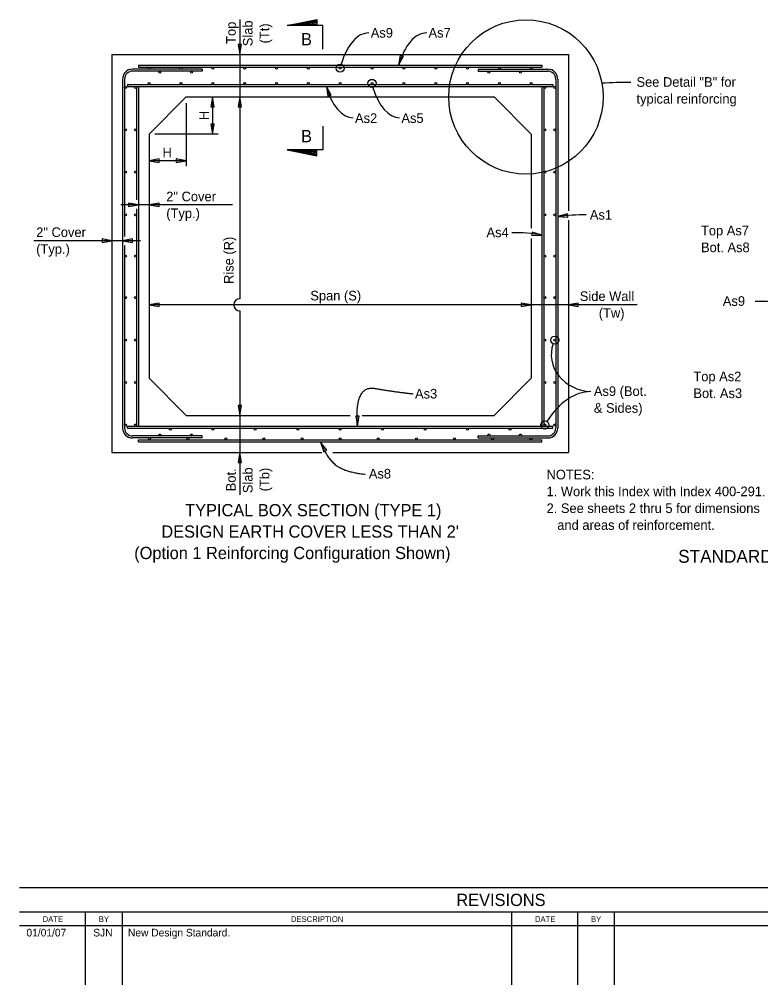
# Model space of a CAD drawing. Extents: x 10340.6 to 10393.7, y 76398.7 to 76426.2.
# Drawn here: x 10340.56 to 10352.2, y 76398.74 to 76413.9 of the extents above; entities that cross this region are included whole.
import ezdxf

# ---------------------------------------------------------------- set-up
doc = ezdxf.new("R2010")
doc.units = 0
for name, color, linetype in [('AdhocPoint_dp', 7, 'Continuous'), ('Border', 7, 'Continuous'), ('Patterning', 7, 'Continuous'), ('PlotBorder_dp', 7, 'Continuous'), ('TextMisc', 7, 'Continuous')]:
    doc.layers.add(name, color=color, linetype=linetype)

msp = doc.modelspace()

# ---------------------------------------------------------------- linework, layer by layer
at = {"layer": 'AdhocPoint_dp'}
for p, q in [((10342.427, 76413.179), (10348.76, 76413.179)), ((10342.427, 76413.179), (10342.427, 76413.148)), ((10342.427, 76413.148), (10348.76, 76413.148)), ((10348.76, 76413.179), (10348.76, 76413.148)), ((10343.427, 76413.116), (10342.333, 76413.116)), ((10343.427, 76413.085), (10342.333, 76413.085)), ((10343.427, 76413.116), (10343.427, 76413.085)), ((10347.76, 76413.116), (10348.854, 76413.116)), ((10347.76, 76413.116), (10347.76, 76413.085)), ((10347.76, 76413.085), (10348.854, 76413.085)), ((10342.177, 76412.96), (10342.177, 76407.481)), ((10342.208, 76412.96), (10342.208, 76410.487)), ((10342.252, 76412.877), (10348.935, 76412.877)), ((10342.252, 76412.877), (10342.252, 76412.845)), ((10342.252, 76412.845), (10348.935, 76412.845)), ((10342.396, 76412.845), (10342.396, 76411.063)), ((10342.427, 76412.845), (10342.427, 76407.512)), ((10348.76, 76412.845), (10348.76, 76407.512)), ((10348.76, 76412.845), (10348.76, 76407.799)), ((10348.791, 76412.845), (10348.791, 76407.512)), ((10348.935, 76412.877), (10348.935, 76412.845)), ((10348.979, 76412.96), (10348.979, 76407.481)), ((10349.01, 76412.96), (10349.01, 76407.481)), ((10342.396, 76410.921), (10342.396, 76407.512)), ((10342.208, 76410.346), (10342.208, 76407.481)), ((10342.252, 76407.512), (10348.935, 76407.512)), ((10342.252, 76407.481), (10342.252, 76407.512)), ((10348.935, 76407.481), (10348.935, 76407.512)), ((10342.252, 76407.481), (10348.935, 76407.481)), ((10343.427, 76407.356), (10342.333, 76407.356)), ((10343.427, 76407.325), (10342.333, 76407.325)), ((10342.427, 76407.293), (10348.76, 76407.293)), ((10342.427, 76407.262), (10342.427, 76407.293)), ((10342.427, 76407.262), (10348.76, 76407.262)), ((10343.427, 76407.325), (10343.427, 76407.356)), ((10347.76, 76407.325), (10347.76, 76407.356)), ((10347.76, 76407.356), (10348.854, 76407.356)), ((10347.76, 76407.325), (10348.854, 76407.325)), ((10348.76, 76407.262), (10348.76, 76407.293))]:
    msp.add_line(p, q, dxfattribs=at)
for centre in [(10342.594, 76413.132), (10343.094, 76413.132), (10343.594, 76413.132), (10344.094, 76413.132), (10344.594, 76413.132), (10345.094, 76413.132), (10345.594, 76413.132), (10346.094, 76413.132), (10346.594, 76413.132), (10347.094, 76413.132), (10347.594, 76413.132), (10348.094, 76413.132), (10348.594, 76413.132), (10342.76, 76413.07), (10343.26, 76413.07), (10347.927, 76413.07), (10348.427, 76413.07), (10342.224, 76412.83), (10342.38, 76412.83), (10342.594, 76412.892), (10343.094, 76412.892), (10343.594, 76412.892), (10344.094, 76412.892), (10344.594, 76412.892), (10345.094, 76412.892), (10345.594, 76412.892), (10346.094, 76412.892), (10346.594, 76412.892), (10347.094, 76412.892), (10347.594, 76412.892), (10348.094, 76412.892), (10348.594, 76412.892), (10348.807, 76412.83), (10348.963, 76412.83), (10342.224, 76412.163), (10342.38, 76412.163), (10348.807, 76412.163), (10348.963, 76412.163), (10342.224, 76411.497), (10342.38, 76411.497), (10348.807, 76411.497), (10348.963, 76411.497), (10342.224, 76410.83), (10342.38, 76410.83), (10348.807, 76410.83), (10348.963, 76410.83), (10342.224, 76410.179), (10342.38, 76410.179), (10348.807, 76410.179), (10348.963, 76410.179), (10342.224, 76409.528), (10342.38, 76409.528), (10348.807, 76409.528), (10348.963, 76409.528), (10342.224, 76408.861), (10342.38, 76408.861), (10348.807, 76408.861), (10348.963, 76408.861), (10342.224, 76408.194), (10342.38, 76408.194), (10348.807, 76408.194), (10348.963, 76408.194), (10342.224, 76407.528), (10342.38, 76407.528), (10348.807, 76407.528), (10348.963, 76407.528), (10342.76, 76407.371), (10342.927, 76407.465), (10343.26, 76407.371), (10343.593, 76407.465), (10344.26, 76407.465), (10344.927, 76407.465), (10345.594, 76407.465), (10346.26, 76407.465), (10346.927, 76407.465), (10347.594, 76407.465), (10347.927, 76407.371), (10348.26, 76407.465), (10348.427, 76407.371), (10342.601, 76407.309), (10343.2, 76407.309), (10343.798, 76407.309), (10344.397, 76407.309), (10344.995, 76407.309), (10345.594, 76407.309), (10346.192, 76407.309), (10346.79, 76407.309), (10347.389, 76407.309), (10347.987, 76407.309), (10348.586, 76407.309)]:
    msp.add_circle(centre, 0.0156, dxfattribs=at)
for centre, radius, start, end in [((10342.333, 76412.96), 0.156, 90.0001, 179.9999), ((10342.333, 76412.96), 0.125, 90, 180), ((10348.854, 76412.96), 0.156, 0.0001, 89.9999), ((10348.854, 76412.96), 0.125, 0, 90), ((10342.333, 76407.481), 0.156, 180.0001, 269.9999), ((10342.333, 76407.481), 0.125, 180, 270), ((10348.854, 76407.481), 0.125, 270, 0), ((10348.854, 76407.481), 0.156, 270.0001, 359.9999)]:
    msp.add_arc(centre, radius, start, end, dxfattribs=at)
at = {"layer": 'Border'}
for p, q in [((10356.014, 76400.262), (10340.556, 76400.262)), ((10356.014, 76399.876), (10340.556, 76399.876)), ((10341.588, 76399.876), (10341.588, 76398.74)), ((10342.168, 76399.876), (10342.168, 76398.74)), ((10348.285, 76399.876), (10348.285, 76398.74)), ((10349.318, 76399.876), (10349.318, 76398.74)), ((10349.898, 76399.876), (10349.898, 76398.74)), ((10340.556, 76399.671), (10356.014, 76399.671))]:
    msp.add_line(p, q, dxfattribs=at)
at = {"layer": 'Patterning'}
for points in [[(10345.864, 76407.512), (10345.818, 76408.158), (10346.456, 76408.048), (10346.74, 76408.018)], [(10345.283, 76407.256), (10345.408, 76406.969), (10345.701, 76406.785), (10345.985, 76406.755)]]:
    msp.add_open_spline(points, degree=2, dxfattribs=at)
at = {"layer": 'PlotBorder_dp'}
for p, q in [((10342.01, 76413.345), (10349.177, 76413.345)), ((10342.01, 76413.345), (10342.01, 76407.096)), ((10349.177, 76413.345), (10349.177, 76410.891)), ((10342.594, 76412.096), (10343.177, 76412.679)), ((10343.177, 76412.679), (10348.01, 76412.679)), ((10348.594, 76412.096), (10348.01, 76412.679)), ((10342.594, 76412.096), (10342.594, 76408.262)), ((10348.594, 76412.096), (10348.594, 76410.618)), ((10349.177, 76410.745), (10349.177, 76407.096)), ((10348.594, 76410.454), (10348.594, 76408.262)), ((10342.594, 76408.262), (10343.177, 76407.679)), ((10348.594, 76408.262), (10348.01, 76407.679)), ((10343.177, 76407.679), (10345.749, 76407.679)), ((10345.939, 76407.679), (10348.01, 76407.679)), ((10342.01, 76407.096), (10345.308, 76407.096)), ((10345.479, 76407.096), (10349.177, 76407.096))]:
    msp.add_line(p, q, dxfattribs=at)
at = {"layer": 'TextMisc'}
for p, q in [((10344.016, 76413.898), (10344.016, 76413.345)), ((10344.76, 76413.802), (10345.229, 76413.885)), ((10345.229, 76413.875), (10344.76, 76413.802)), ((10344.76, 76413.802), (10345.229, 76413.862)), ((10345.229, 76413.848), (10344.76, 76413.802)), ((10344.76, 76413.802), (10345.229, 76413.835)), ((10345.229, 76413.82), (10344.76, 76413.802)), ((10344.016, 76413.345), (10344.016, 76412.679)), ((10343.588, 76412.679), (10343.588, 76412.096)), ((10344.016, 76412.679), (10344.016, 76409.509)), ((10343.177, 76412.584), (10343.177, 76411.592)), ((10343.679, 76412.096), (10342.682, 76412.096)), ((10345.229, 76411.83), (10344.76, 76411.847)), ((10344.76, 76411.847), (10345.229, 76411.815)), ((10345.229, 76411.801), (10344.76, 76411.847)), ((10344.76, 76411.847), (10345.229, 76411.787)), ((10345.229, 76411.775), (10344.76, 76411.847)), ((10344.76, 76411.847), (10345.229, 76411.765)), ((10343.177, 76411.678), (10342.594, 76411.678)), ((10342.427, 76410.984), (10342.15, 76410.984)), ((10342.594, 76410.984), (10342.427, 76410.984)), ((10343.902, 76410.984), (10342.594, 76410.984)), ((10342.01, 76410.422), (10340.786, 76410.422)), ((10342.177, 76410.422), (10342.01, 76410.422)), ((10342.457, 76410.422), (10342.177, 76410.422)), ((10348.594, 76409.415), (10342.594, 76409.415)), ((10349.177, 76409.415), (10348.594, 76409.415)), ((10350.255, 76409.415), (10349.177, 76409.415)), ((10344.016, 76409.321), (10344.016, 76407.679)), ((10344.016, 76407.679), (10344.016, 76407.096)), ((10344.016, 76407.096), (10344.016, 76406.429))]:
    msp.add_line(p, q, dxfattribs=at)
for points in [[(10345.323, 76413.427), (10345.323, 76413.802), (10344.76, 76413.802), (10345.229, 76413.896), (10345.229, 76413.802)], [(10345.323, 76412.222), (10345.323, 76411.847), (10344.76, 76411.847), (10345.229, 76411.753), (10345.229, 76411.847)]]:
    msp.add_lwpolyline(points, dxfattribs=at)
for points in [[(10344.016, 76413.345), (10344.043, 76413.502), (10343.99, 76413.502)], [(10346.512, 76413.179), (10346.587, 76413.318), (10346.537, 76413.335)], [(10345.377, 76412.845), (10345.401, 76412.689), (10345.451, 76412.706)], [(10343.588, 76412.679), (10343.562, 76412.523), (10343.615, 76412.523)], [(10344.016, 76412.679), (10343.99, 76412.523), (10344.043, 76412.523)], [(10343.588, 76412.096), (10343.615, 76412.252), (10343.562, 76412.252)], [(10342.594, 76411.678), (10342.75, 76411.652), (10342.75, 76411.705)], [(10343.177, 76411.678), (10343.021, 76411.705), (10343.021, 76411.652)], [(10342.427, 76410.984), (10342.271, 76411.01), (10342.271, 76410.958)], [(10342.594, 76410.984), (10342.75, 76410.958), (10342.75, 76411.01)], [(10349.01, 76410.801), (10349.168, 76410.791), (10349.163, 76410.843)], [(10348.76, 76410.51), (10348.609, 76410.557), (10348.602, 76410.504)], [(10342.01, 76410.422), (10341.854, 76410.449), (10341.854, 76410.396)], [(10342.177, 76410.422), (10342.333, 76410.396), (10342.333, 76410.449)], [(10342.594, 76409.415), (10342.75, 76409.388), (10342.75, 76409.441)], [(10348.594, 76409.415), (10348.437, 76409.441), (10348.437, 76409.388)], [(10349.177, 76409.415), (10349.333, 76409.388), (10349.333, 76409.441)], [(10344.016, 76407.679), (10344.043, 76407.835), (10343.99, 76407.835)], [(10345.864, 76407.512), (10345.893, 76407.668), (10345.841, 76407.669)], [(10345.283, 76407.256), (10345.335, 76407.107), (10345.382, 76407.132)], [(10344.016, 76407.096), (10343.99, 76406.939), (10344.043, 76406.939)]]:
    msp.add_lwpolyline(points, close=True, dxfattribs=at)
for centre, radius in [((10348.51, 76412.679), 1.212), ((10345.594, 76413.132), 0.0638), ((10346.094, 76412.892), 0.0638), ((10348.963, 76408.861), 0.0638), ((10348.807, 76407.528), 0.0638)]:
    msp.add_circle(centre, radius, dxfattribs=at)
for centre, radius, start, end in [((10350.11, 76407.214), 5.694, 89.5106, 94.0936), ((10349.418, 76407.612), 3.216, 89.2818, 97.2882), ((10348.326, 76407.994), 2.553, 80.213, 90.7866), ((10344.016, 76409.415), 0.0939, 90, 270), ((10352.153, 76412.326), 2.855, 269.165, 283.9846)]:
    msp.add_arc(centre, radius, start, end, dxfattribs=at)
for centre, major_axis, ratio, start_param, end_param in [((10346.034, 76412.726), (-0.012, -0.959), 0.511154, 3.141593, 4.208834), ((10346.94, 76412.726), (-0.012, -0.959), 0.511154, 3.141593, 4.226382), ((10345.809, 76413.312), (-0.012, -0.959), 0.511154, 5.227094, 6.283185), ((10346.537, 76413.312), (-0.012, -0.959), 0.511154, 5.245289, 6.283185), ((10349.556, 76408.623), (-0.648, 0.03), 0.879421, 6.015626, 7.853982), ((10349.549, 76406.05), (0.019, -2.003), 0.541712, 3.141593, 3.836225)]:
    msp.add_ellipse(centre, major_axis=major_axis, ratio=ratio, start_param=start_param, end_param=end_param, dxfattribs=at)

# ---------------------------------------------------------------- texts
at = {"layer": 'Patterning'}
for s, height, p in [('As9', 0.1512, (10346.074, 76413.611)), ('As7', 0.1512, (10346.981, 76413.611)), ('B', 0.192, (10344.98, 76413.49)), ('As2', 0.1512, (10345.827, 76412.271)), ('As5', 0.1512, (10346.555, 76412.271)), ('B', 0.192, (10344.98, 76411.968)), ('H', 0.151, (10342.804, 76411.733)), ('As1', 0.1512, (10349.514, 76410.753)), ('As4', 0.1512, (10347.891, 76410.477)), ('Span (S)', 0.1512, (10345.125, 76409.484)), ('As3', 0.1512, (10346.769, 76407.944)), ('As8', 0.1512, (10346.044, 76406.688)), ('STANDARD PRECAST BOX CULVERT WITH 2" CONCRETE COVER', 0.2016, (10350.901, 76405.365)), ('REVISIONS', 0.1925, (10347.417, 76399.975)), ('BY', 0.0901, (10341.804, 76399.724)), ('BY', 0.0901, (10349.533, 76399.724)), ('01/01/07', 0.12, (10340.668, 76399.497)), ('SJN', 0.12, (10341.717, 76399.497)), ('New Design Standard.', 0.12, (10342.262, 76399.497))]:
    msp.add_text(s, height=height, dxfattribs=at).set_placement(p)
for s, height, rotation, p in [('H', 0.151, 90, (10343.532, 76412.315)), ('Rise (R)', 0.1512, 90, (10343.919, 76409.743)), ('DATE', 0.0897, 359.8693, (10340.922, 76399.725)), ('DESCRIPTION', 0.09005, 0.0498, (10344.82, 76399.724)), ('DATE', 0.0897, 359.8693, (10348.652, 76399.725))]:
    msp.add_text(s, height=height, rotation=rotation, dxfattribs=at).set_placement(p)
at = {"layer": 'TextMisc'}
for s, p in [('Top', (10343.954, 76413.513)), ('Slab', (10344.218, 76413.476)), ('(Tt)', (10344.482, 76413.52)), ('Bot.', (10343.954, 76406.488)), ('Slab', (10344.218, 76406.458)), ('(Tb)', (10344.482, 76406.486))]:
    msp.add_text(s, height=0.1512, rotation=90, dxfattribs=at).set_placement(p)
for s, height, p in [('See Detail "B" for', 0.1512, (10350.246, 76412.839)), ('typical reinforcing', 0.1512, (10350.246, 76412.575)), ('2" Cover', 0.1512, (10342.863, 76411.041)), ('(Typ.)', 0.1512, (10342.863, 76410.777)), ('2" Cover', 0.1512, (10340.821, 76410.48)), ('Top As7', 0.1512, (10351.259, 76410.506)), ('Bot. As8', 0.1512, (10351.259, 76410.242)), ('(Typ.)', 0.1512, (10340.821, 76410.216)), ('Side Wall', 0.1512, (10349.356, 76409.475)), ('As9', 0.1512, (10351.602, 76409.399)), ('(Tw)', 0.1512, (10349.654, 76409.211)), ('Top As2', 0.1512, (10351.14, 76408.215)), ('As9 (Bot.', 0.1512, (10349.577, 76407.984)), ('Bot. As3', 0.1512, (10351.14, 76407.951)), ('& Sides)', 0.1512, (10349.577, 76407.72)), ('NOTES:', 0.1512, (10348.834, 76406.674)), ('1. Work this Index with Index 400-291.', 0.1512, (10348.834, 76406.41)), ('TYPICAL BOX SECTION (TYPE 1)', 0.192, (10343.16, 76406.095)), ('2. See sheets 2 thru 5 for dimensions', 0.1512, (10348.834, 76406.146)), ('   and areas of reinforcement.', 0.1512, (10348.834, 76405.882)), ("DESIGN EARTH COVER LESS THAN 2'", 0.192, (10342.786, 76405.759)), ('(Option 1 Reinforcing Configuration Shown)', 0.192, (10342.36, 76405.423))]:
    msp.add_text(s, height=height, dxfattribs=at).set_placement(p)

doc.saveas('drawing.dxf')
